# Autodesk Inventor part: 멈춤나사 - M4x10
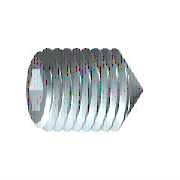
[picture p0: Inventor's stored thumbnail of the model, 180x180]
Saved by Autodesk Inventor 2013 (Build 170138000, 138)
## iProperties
Created: 2012-02
Part Number: 멈춤나사 - M4x10
Material: 강철, 연강
Description: 6각 소켓 머리 없는 멈춤 나사
Document SubType Name: Modeling
Standard: KS B 1028
Designer: mduedu
Standards Organization: KS
Language: ko-KR
Size Designation: 원추점 M4x10
Categories: <MemberInstance><Categories><Category DisplayName="조임쇠" InternalName="e4da775c-781d-43d5-af7c-5136215cf5a6" Mnemonic="FSTN"><Category DisplayName="볼트" InternalN
Density: 1 g/cm^3
Author: mduedu
IsCustomPart: 1
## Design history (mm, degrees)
sketch "스케치1"
  geometry: L1 (0, 0)-(6.833, 0); L2 (10, 1.155)-(10, 2); L3 (10, 2)-(0, 2); L4 (10, 1.155)-(7.5, 1.155); L5 (7.5, 1.155)-(6.833, 0); L6 (0, -0.4)-(0, 2.4) reference; L7 (0, 2)-(0, 0)
  constraints: 13 end point, 3 parallel, 1 collinear, 1 perpendicular, 1 point on line
  dimensions: "d0" = 2.5 distance of L2.start L4.end (= INTI); "d1" = 60 deg angle of L5 L1; "d2" = 4 diameter of L3 L1 (= NND); "d3" = 2.3094 diameter of L4 L1 (= 1.1547 x SW); "d5" = 10 distance from line of L2 L3.end (= NLG)
revolve "본체" sketch "스케치1" stored, may be unused: angle "d6" = 90 deg
sketch "스케치2"
  geometry: L1 (-0.577, 1)-(0.577, 1); L2 (0.577, 1)-(1.155, 0); L3 (1.155, 0)-(0.577, -1); L4 (0.577, -1)-(-0.577, -1); L5 (-0.577, -1)-(-1.155, 0); L6 (-1.155, 0)-(-0.577, 1); 3 further points
  constraints: 12 end point, 1 coincident, 1 horizontal, 13 other
extrude "슬롯" join sketch "스케치2" taper "d7" = 0 deg; stored distance "d21" = 10
workaxis "Work Axis1"
workplane "Work Plane1"
body "Solid1"
feature "스레드" dims "d12" = 10 (= NLG), "d13" = 0
chamfer "모따기1" distance "d8" = 1.8 (computed from NND, SPD, FAWI); stored, may be unused: angle "d9" = 45 deg (= FAWI), second distance "d34" = 1.8 (computed from NND, SPD, FAWI)
chamfer "모따기2" distance "d10" = 0.42941 (= -0.5 x GD1 + 0.5 x NND); stored, may be unused: angle "d11" = 45 deg (= FAWI), second distance "d35" = 0.42941 (= -0.5 x GD1 + 0.5 x NND)
other parameters: "NND" = 4 [user parameter; used in 5 equation terms], "NLG" = 10 [user parameter; used in 2 equation terms], "INTI" = 2.5 [user parameter; used in 1 equation term], "FAWI" = 45 deg [user parameter; used in 4 equation terms], "SW" = 2 [user parameter; used in 2 equation terms], "GD1" = 3.14117 (= THREADDIA - 1.2269 x PTC) [user parameter; used in 2 equation terms], "d4" = 0, "FAWI1" = 45 deg [user parameter], "SPD" = 0.4 [user parameter; used in 2 equation terms], "d36" = 0, "d37" = 0, "GUL" = 0.42941 (= 0.61345 x PTC) [user parameter], "TPU" = 14.28571 (computed from PTC) [user parameter], "TOA" = 30 deg [user parameter], "THREADDIA" = 4 [user parameter; used in 1 equation term], "PTC" = 0.7 [user parameter; used in 4 equation terms], "GAL" = 0.42941 (= 0.61345 x PTC) [user parameter], "E0" = 2.31 (= 1.155 x SW) [user parameter]
